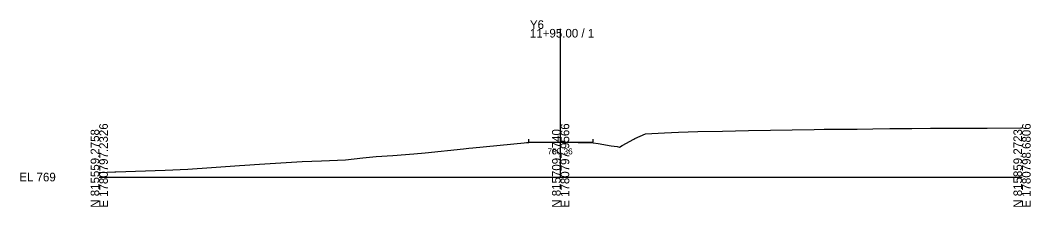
# Model space of a CAD drawing. Extents: x -26 to 1603, y -10 to 6024.
# Drawn here: x 1274.3 to 1602.8, y -9.7 to 51.1 of the extents above; entities that cross this region are included whole.
import ezdxf

# ---------------------------------------------------------------- set-up
doc = ezdxf.new("R2010")
doc.units = 0
for name, color, linetype in [('Exist Cross Section Cell', 7, 'Continuous'), ('Exist XS Center Line Elevation Label', 7, 'Continuous'), ('Exist XS Ground Line', 7, 'Continuous'), ('Prop XS EOT Tick Mark', 7, 'Continuous'), ('Prop XS Finish Grade Pavement', 7, 'Continuous')]:
    doc.layers.add(name, color=color, linetype=linetype)

msp = doc.modelspace()

# ---------------------------------------------------------------- linework, layer by layer
at = {"layer": 'Exist Cross Section Cell'}
for p, q in [((1450, 0), (1450, 48.22)), ((1300, 0), (1450, 0)), ((1450, 0), (1600, 0))]:
    msp.add_line(p, q, dxfattribs=at)
at = {"layer": 'Exist XS Ground Line'}
for p, q in [((1474.11, 12.55), (1477.55, 14.07)), ((1477.55, 14.07), (1483.8, 14.42)), ((1483.8, 14.42), (1488.26, 14.59)), ((1488.26, 14.59), (1494.65, 14.82)), ((1494.65, 14.82), (1502.6, 14.98)), ((1502.6, 14.98), (1511.03, 15.11)), ((1511.03, 15.11), (1532.43, 15.47)), ((1532.43, 15.47), (1535.72, 15.57)), ((1535.72, 15.57), (1539.85, 15.61)), ((1539.85, 15.61), (1546.36, 15.64)), ((1546.36, 15.64), (1551.51, 15.73)), ((1551.51, 15.73), (1557.03, 15.81)), ((1557.03, 15.81), (1564.12, 15.83)), ((1564.12, 15.83), (1570.25, 15.89)), ((1570.25, 15.89), (1587.86, 15.9)), ((1587.86, 15.9), (1588.62, 15.91)), ((1588.62, 15.91), (1599.61, 16.07)), ((1599.61, 16.07), (1600, 16.07)), ((1421.45, 9.5), (1438.11, 11.13)), ((1438.11, 11.13), (1438.93, 11.21)), ((1438.93, 11.21), (1439.71, 11.26)), ((1439.71, 11.26), (1450.2, 11.36)), ((1450.2, 11.36), (1450.68, 11.35)), ((1450.68, 11.35), (1460.58, 11.18)), ((1460.58, 11.18), (1462.2, 10.92)), ((1462.2, 10.92), (1466.39, 10.19)), ((1466.39, 10.19), (1468.35, 9.93)), ((1468.35, 9.93), (1469.14, 9.76)), ((1469.14, 9.76), (1470.03, 10.25)), ((1470.03, 10.25), (1473.74, 12.36)), ((1473.74, 12.36), (1474.11, 12.55)), ((1385.71, 6.23), (1390.07, 6.66)), ((1390.07, 6.66), (1395.44, 7.05)), ((1395.44, 7.05), (1402.29, 7.55)), ((1402.29, 7.55), (1405.91, 7.86)), ((1405.91, 7.86), (1418.46, 9.22)), ((1418.46, 9.22), (1420.15, 9.39)), ((1420.15, 9.39), (1421.45, 9.5)), ((1336.47, 3.08), (1345.61, 3.74)), ((1345.61, 3.74), (1347.33, 3.86)), ((1347.33, 3.86), (1352.15, 4.15)), ((1352.15, 4.15), (1366, 5.05)), ((1366, 5.05), (1372.23, 5.31)), ((1372.23, 5.31), (1380.04, 5.63)), ((1380.04, 5.63), (1385.71, 6.23)), ((1300, 1.46), (1305.05, 1.71)), ((1305.05, 1.71), (1305.38, 1.72)), ((1305.38, 1.72), (1321.38, 2.27)), ((1321.38, 2.27), (1328.85, 2.61)), ((1328.85, 2.61), (1336.47, 3.08))]:
    msp.add_line(p, q, dxfattribs=at)
at = {"layer": 'Prop XS EOT Tick Mark'}
for p, q in [((1439.71, 11.38), (1439.71, 12.38)), ((1460.58, 11.31), (1460.58, 12.31))]:
    msp.add_line(p, q, dxfattribs=at)
at = {"layer": 'Prop XS Finish Grade Pavement'}
for p, q in [((1439.71, 11.38), (1450.2, 11.48)), ((1450.2, 11.48), (1450.68, 11.48)), ((1450.68, 11.48), (1460.58, 11.31))]:
    msp.add_line(p, q, dxfattribs=at)

# ---------------------------------------------------------------- texts
at = {"layer": 'Exist Cross Section Cell'}
for s, p in [('Y6', (1440, 48.22)), ('11+95.00 / 1', (1440, 45.42)), ('EL 769', (1274, -1.4))]:
    msp.add_text(s, height=2.8, dxfattribs=at).set_placement(p)
for s, p in [('E 1780797.2326', (1302.8, -10)), ('E 1780797.9566', (1452.8, -10)), ('E 1780798.6806', (1602.8, -10)), ('N 815559.2758', (1300, -10)), ('N 815709.2740', (1450, -10)), ('N 815859.2723', (1600, -10))]:
    msp.add_text(s, height=2.8, rotation=90, dxfattribs=at).set_placement(p)
at = {"layer": 'Exist XS Center Line Elevation Label'}
msp.add_text('780.36', height=2, dxfattribs=at).set_placement((1445.73, 7.36))

doc.saveas('drawing.dxf')
